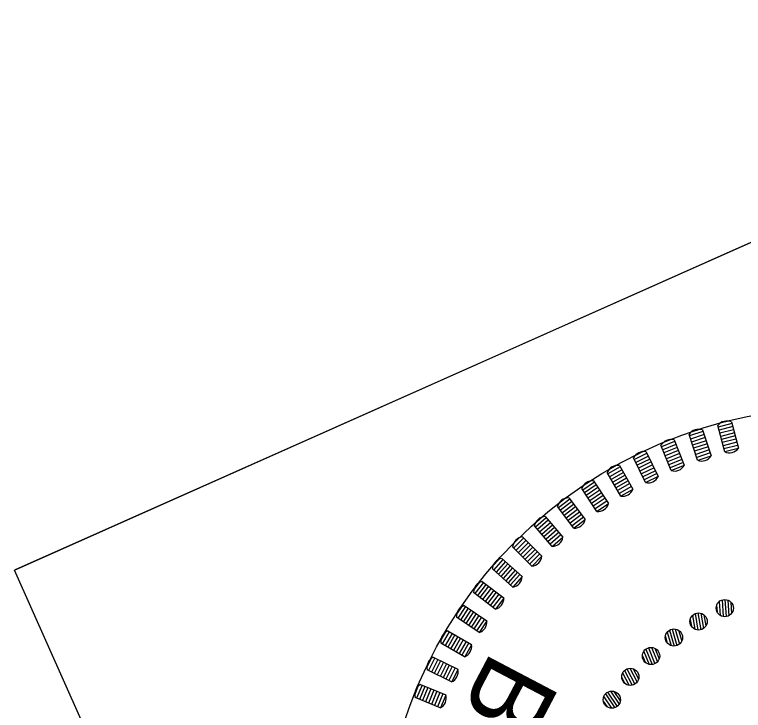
# Model space of a CAD drawing. Extents: x 885268 to 886953, y 552794 to 554777.
# Drawn here: x 886759.5 to 886819.5, y 553269.8 to 553327.1 of the extents above; entities that cross this region are included whole.
import ezdxf

# ---------------------------------------------------------------- set-up
doc = ezdxf.new("R2010")
doc.units = 0
doc.layers.add('Sheet PE Seal Cell', color=7, linetype='Continuous')
doc.layers.add('Sheet Plan CELL', color=7, linetype='Continuous')

msp = doc.modelspace()

# ---------------------------------------------------------------- linework, layer by layer
at = {"layer": 'Sheet PE Seal Cell'}
for p, q in [((886817.956, 553291.104), (886817.391, 553293.28)), ((886818.551, 553293.439), (886817.426, 553293.147)), ((886818.265, 553293.639), (886817.579, 553293.461)), ((886818.517, 553293.572), (886819.082, 553291.396)), ((886816.169, 553292.776), (886815.065, 553292.411)), ((886815.87, 553292.957), (886815.197, 553292.734)), ((886816.126, 553292.906), (886816.833, 553290.772)), ((886818.618, 553293.183), (886817.493, 553292.89)), ((886818.685, 553292.926), (886817.559, 553292.634)), ((886818.751, 553292.669), (886817.626, 553292.377)), ((886813.525, 553292.118), (886812.869, 553291.851)), ((886813.784, 553292.084), (886814.631, 553290.002)), ((886815.729, 553290.407), (886815.022, 553292.541)), ((886816.253, 553292.525), (886815.149, 553292.159)), ((886816.336, 553292.273), (886815.232, 553291.907)), ((886818.818, 553292.412), (886817.692, 553292.12)), ((886818.885, 553292.155), (886817.759, 553291.863)), ((886813.554, 553289.564), (886812.707, 553291.647)), ((886813.836, 553291.958), (886812.758, 553291.52)), ((886813.936, 553291.712), (886812.858, 553291.274)), ((886814.036, 553291.466), (886812.958, 553291.028)), ((886816.419, 553292.021), (886815.316, 553291.655)), ((886816.503, 553291.769), (886815.399, 553291.403)), ((886816.586, 553291.517), (886815.483, 553291.151)), ((886818.951, 553291.898), (886817.826, 553291.606)), ((886819.018, 553291.641), (886817.892, 553291.349)), ((886811.562, 553290.986), (886810.516, 553290.478)), ((886811.241, 553291.126), (886810.604, 553290.816)), ((886811.502, 553291.109), (886812.484, 553289.087)), ((886814.135, 553291.22), (886813.058, 553290.782)), ((886814.235, 553290.974), (886813.158, 553290.536)), ((886816.67, 553291.265), (886815.566, 553290.899)), ((886816.753, 553291.013), (886815.65, 553290.648)), ((886819.071, 553291.381), (886817.973, 553291.096)), ((886811.438, 553288.579), (886810.456, 553290.601)), ((886811.677, 553290.748), (886810.632, 553290.239)), ((886811.793, 553290.509), (886810.748, 553290.001)), ((886811.909, 553290.27), (886810.863, 553289.762)), ((886814.335, 553290.728), (886813.258, 553290.291)), ((886814.435, 553290.483), (886813.358, 553290.045)), ((886814.535, 553290.237), (886813.458, 553289.799)), ((886816.823, 553290.757), (886815.747, 553290.4)), ((886809.357, 553289.867), (886808.346, 553289.291)), ((886809.028, 553289.985), (886808.412, 553289.634)), ((886809.488, 553289.636), (886808.478, 553289.06)), ((886809.289, 553289.986), (886810.403, 553288.033)), ((886812.025, 553290.032), (886810.979, 553289.523)), ((886812.141, 553289.793), (886811.095, 553289.285)), ((886814.622, 553289.986), (886813.571, 553289.559)), ((886809.393, 553287.457), (886808.279, 553289.41)), ((886809.619, 553289.406), (886808.609, 553288.83)), ((886809.751, 553289.175), (886808.741, 553288.599)), ((886812.257, 553289.554), (886811.211, 553289.046)), ((886812.373, 553289.316), (886811.327, 553288.807)), ((886812.476, 553289.071), (886811.456, 553288.575)), ((886807.23, 553288.604), (886806.261, 553287.962)), ((886806.894, 553288.7), (886806.304, 553288.309)), ((886807.155, 553288.718), (886808.395, 553286.843)), ((886809.882, 553288.945), (886808.872, 553288.369)), ((886810.014, 553288.714), (886809.004, 553288.138)), ((886810.145, 553288.484), (886809.135, 553287.908)), ((886807.426, 553286.202), (886806.185, 553288.076)), ((886807.377, 553288.383), (886806.407, 553287.741)), ((886807.523, 553288.161), (886806.553, 553287.52)), ((886807.67, 553287.94), (886806.7, 553287.298)), ((886810.277, 553288.253), (886809.267, 553287.677)), ((886810.396, 553288.016), (886809.411, 553287.454)), ((886804.851, 553287.277), (886804.287, 553286.848)), ((886805.109, 553287.312), (886806.471, 553285.524)), ((886807.816, 553287.719), (886806.846, 553287.077)), ((886807.962, 553287.497), (886806.993, 553286.856)), ((886808.109, 553287.276), (886807.139, 553286.634)), ((886805.192, 553287.203), (886804.267, 553286.499)), ((886805.353, 553286.992), (886804.428, 553286.288)), ((886805.514, 553286.781), (886804.588, 553286.077)), ((886808.255, 553287.055), (886807.286, 553286.413)), ((886808.39, 553286.826), (886807.444, 553286.2)), ((886805.546, 553284.819), (886804.184, 553286.608)), ((886805.674, 553286.57), (886804.749, 553285.866)), ((886805.835, 553286.359), (886804.91, 553285.654)), ((886805.996, 553286.148), (886805.071, 553285.443)), ((886802.906, 553285.722), (886802.372, 553285.257)), ((886803.251, 553285.671), (886802.375, 553284.907)), ((886803.426, 553285.471), (886802.549, 553284.707)), ((886803.161, 553285.774), (886804.638, 553284.08)), ((886806.157, 553285.937), (886805.231, 553285.232)), ((886806.317, 553285.725), (886805.392, 553285.021)), ((886806.467, 553285.506), (886805.564, 553284.819)), ((886803.762, 553283.316), (886802.285, 553285.01)), ((886803.6, 553285.271), (886802.723, 553284.507)), ((886803.774, 553285.071), (886802.898, 553284.307)), ((886803.949, 553284.871), (886803.072, 553284.107)), ((886804.123, 553284.671), (886803.246, 553283.907)), ((886804.297, 553284.471), (886803.421, 553283.707)), ((886804.472, 553284.271), (886803.595, 553283.507)), ((886801.067, 553284.042), (886800.565, 553283.542)), ((886801.416, 553284.014), (886800.591, 553283.194)), ((886801.603, 553283.826), (886800.779, 553283.006)), ((886801.79, 553283.638), (886800.966, 553282.818)), ((886801.319, 553284.111), (886802.905, 553282.518)), ((886804.635, 553284.061), (886803.78, 553283.316)), ((886802.081, 553281.697), (886800.495, 553283.291)), ((886801.977, 553283.45), (886801.153, 553282.63)), ((886802.164, 553283.262), (886801.34, 553282.441)), ((886802.352, 553283.074), (886801.527, 553282.253)), ((886802.539, 553282.886), (886801.714, 553282.065)), ((886802.726, 553282.697), (886801.902, 553281.877)), ((886802.903, 553282.499), (886802.099, 553281.699)), ((886799.344, 553282.244), (886798.876, 553281.712)), ((886799.694, 553282.239), (886798.925, 553281.366)), ((886799.893, 553282.064), (886799.125, 553281.191)), ((886800.092, 553281.889), (886799.324, 553281.016)), ((886799.591, 553282.33), (886801.278, 553280.845)), ((886800.51, 553279.972), (886798.823, 553281.457)), ((886800.291, 553281.713), (886799.523, 553280.84)), ((886800.49, 553281.538), (886799.722, 553280.665)), ((886800.69, 553281.363), (886799.921, 553280.49)), ((886800.889, 553281.187), (886800.121, 553280.315)), ((886801.088, 553281.012), (886800.32, 553280.139)), ((886801.278, 553280.826), (886800.528, 553279.975)), ((886797.744, 553280.336), (886797.312, 553279.775)), ((886798.093, 553280.355), (886797.384, 553279.433)), ((886798.303, 553280.193), (886797.594, 553279.271)), ((886798.513, 553280.031), (886797.805, 553279.109)), ((886797.984, 553280.438), (886799.766, 553279.068)), ((886799.057, 553278.146), (886797.275, 553279.516)), ((886798.724, 553279.869), (886798.015, 553278.947)), ((886798.934, 553279.708), (886798.225, 553278.786)), ((886799.144, 553279.546), (886798.436, 553278.624)), ((886799.355, 553279.384), (886798.646, 553278.462)), ((886799.565, 553279.222), (886798.856, 553278.3)), ((886799.767, 553279.049), (886799.075, 553278.15)), ((886817.739, 553278.904), (886817.835, 553277.534)), ((886817.973, 553278.941), (886818.072, 553277.531)), ((886818.213, 553278.895), (886818.304, 553277.61)), ((886796.273, 553278.327), (886795.879, 553277.738)), ((886796.62, 553278.368), (886795.973, 553277.401)), ((886796.84, 553278.221), (886796.194, 553277.254)), ((886796.506, 553278.444), (886798.375, 553277.195)), ((886817.295, 553278.472), (886817.336, 553277.901)), ((886817.511, 553278.778), (886817.592, 553277.627)), ((886818.461, 553278.735), (886818.527, 553277.803)), ((886797.061, 553278.073), (886796.415, 553277.106)), ((886797.282, 553277.926), (886796.635, 553276.959)), ((886797.502, 553277.778), (886796.856, 553276.811)), ((886797.723, 553277.631), (886797.076, 553276.664)), ((886815.299, 553277.628), (886815.5, 553276.492)), ((886815.512, 553277.777), (886815.751, 553276.425)), ((886815.742, 553277.838), (886815.988, 553276.446)), ((886815.985, 553277.817), (886816.209, 553276.549)), ((886816.249, 553277.685), (886816.411, 553276.764)), ((886797.728, 553276.228), (886795.86, 553277.478)), ((886797.943, 553277.483), (886797.297, 553276.516)), ((886798.164, 553277.336), (886797.517, 553276.369)), ((886798.376, 553277.176), (886797.746, 553276.233)), ((886815.117, 553277.3), (886815.216, 553276.737)), ((886813.416, 553276.424), (886813.795, 553275.103)), ((886813.638, 553276.508), (886814.028, 553275.15)), ((886813.882, 553276.513), (886814.238, 553275.275)), ((886794.938, 553276.224), (886794.584, 553275.611)), ((886795.281, 553276.289), (886794.7, 553275.281)), ((886795.511, 553276.156), (886794.93, 553275.149)), ((886795.741, 553276.024), (886795.16, 553275.016)), ((886795.163, 553276.357), (886797.11, 553275.234)), ((886795.971, 553275.891), (886795.39, 553274.884)), ((886813.072, 553275.908), (886813.23, 553275.358)), ((886813.219, 553276.253), (886813.538, 553275.144)), ((886814.158, 553276.408), (886814.416, 553275.51)), ((886796.529, 553274.226), (886794.582, 553275.35)), ((886796.201, 553275.758), (886795.62, 553274.751)), ((886796.431, 553275.626), (886795.85, 553274.618)), ((886796.66, 553275.493), (886796.079, 553274.486)), ((886796.89, 553275.361), (886796.309, 553274.353)), ((886797.113, 553275.215), (886796.546, 553274.233)), ((886811.295, 553274.667), (886811.727, 553273.598)), ((886811.473, 553274.858), (886811.988, 553273.585)), ((886811.684, 553274.965), (886812.214, 553273.655)), ((886811.927, 553274.996), (886812.41, 553273.802)), ((886812.212, 553274.921), (886812.563, 553274.054)), ((886793.745, 553274.039), (886793.432, 553273.403)), ((886794.083, 553274.125), (886793.57, 553273.082)), ((886793.96, 553274.186), (886795.978, 553273.194)), ((886811.185, 553274.309), (886811.399, 553273.779)), ((886794.321, 553274.008), (886793.808, 553272.965)), ((886794.56, 553273.891), (886794.046, 553272.848)), ((886794.798, 553273.774), (886794.284, 553272.731)), ((886795.036, 553273.657), (886794.523, 553272.613)), ((886795.274, 553273.54), (886794.761, 553272.496)), ((886795.512, 553273.423), (886794.999, 553272.379)), ((886795.465, 553272.15), (886793.447, 553273.142)), ((886795.75, 553273.306), (886795.237, 553272.262)), ((886795.982, 553273.175), (886795.481, 553272.158)), ((886809.547, 553272.89), (886810.088, 553271.872)), ((886809.704, 553273.098), (886810.349, 553271.886)), ((886809.903, 553273.226), (886810.567, 553271.979)), ((886810.141, 553273.282), (886810.746, 553272.145)), ((886810.432, 553273.238), (886810.872, 553272.412)), ((886809.474, 553272.522), (886809.743, 553272.017)), ((886792.699, 553271.779), (886792.429, 553271.124)), ((886793.031, 553271.888), (886792.588, 553270.812)), ((886793.276, 553271.786), (886792.833, 553270.711)), ((886792.904, 553271.94), (886794.983, 553271.083)), ((886793.522, 553271.685), (886793.078, 553270.61)), ((886793.767, 553271.584), (886793.324, 553270.509)), ((886794.012, 553271.483), (886793.569, 553270.408)), ((886794.258, 553271.382), (886793.814, 553270.307)), ((886794.503, 553271.281), (886794.06, 553270.206)), ((886794.748, 553271.18), (886794.305, 553270.105)), ((886794.988, 553271.065), (886794.556, 553270.017)), ((886808.128, 553271.163), (886808.897, 553270.024)), ((886808.313, 553271.311), (886809.103, 553270.14)), ((886808.544, 553271.392), (886809.264, 553270.324)), ((886808.838, 553271.378), (886809.362, 553270.603)), ((886794.54, 553270.008), (886792.461, 553270.865)), ((886807.96, 553270.566), (886808.281, 553270.092)), ((886807.994, 553270.939), (886808.639, 553269.983))]:
    msp.add_line(p, q, dxfattribs=at)
for centre, radius in [((886827.4, 553257.054), 37.726), ((886817.963, 553278.232), 0.709), ((886815.805, 553277.132), 0.709), ((886813.775, 553275.812), 0.709), ((886811.893, 553274.287), 0.709), ((886810.182, 553272.575), 0.709), ((886808.658, 553270.692), 0.709)]:
    msp.add_circle(centre, radius, dxfattribs=at)
for centre, radius, start, end in [((886818.146, 553292.686), 0.96, 67.27471, 141.81568), ((886815.814, 553291.998), 0.96, 71.06419, 145.60515), ((886813.533, 553291.158), 0.96, 74.85366, 149.39463), ((886811.313, 553290.168), 0.96, 78.64313, 153.1841), ((886818.342, 553291.933), 0.914, 245.04845, 324.04194), ((886816.059, 553291.259), 0.914, 248.83792, 327.83142), ((886809.162, 553289.034), 0.96, 82.43261, 156.97358), ((886813.826, 553290.436), 0.914, 252.6274, 331.62089), ((886811.653, 553289.468), 0.914, 256.41687, 335.41036), ((886807.091, 553287.76), 0.96, 86.22208, 160.76305), ((886809.548, 553288.358), 0.914, 260.20635, 339.19984), ((886805.109, 553286.352), 0.96, 90.01155, 164.55252), ((886807.521, 553287.111), 0.914, 263.99582, 342.98931), ((886803.225, 553284.816), 0.96, 93.80103, 168.342), ((886805.581, 553285.733), 0.914, 267.78529, 346.77878), ((886801.446, 553283.159), 0.96, 97.5905, 172.13147), ((886803.736, 553284.229), 0.914, 271.57477, 350.56826), ((886801.995, 553282.608), 0.914, 275.36424, 354.35773), ((886799.78, 553281.389), 0.96, 101.37998, 175.92094), ((886800.365, 553280.874), 0.914, 279.15371, 358.14721), ((886798.235, 553279.511), 0.96, 105.16945, 179.71042), ((886798.853, 553279.037), 0.914, 282.94319, 1.93668), ((886796.818, 553277.536), 0.96, 108.95892, 183.49989), ((886797.465, 553277.103), 0.914, 286.73266, 5.72615), ((886795.534, 553275.472), 0.96, 112.7484, 187.28936), ((886796.208, 553275.083), 0.914, 290.52213, 9.51563), ((886794.389, 553273.327), 0.96, 116.53787, 191.07884), ((886795.088, 553272.983), 0.914, 294.31161, 13.3051), ((886793.389, 553271.111), 0.96, 120.32734, 194.86831), ((886794.109, 553270.814), 0.914, 298.10108, 17.09457)]:
    msp.add_arc(centre, radius, start, end, dxfattribs=at)
at = {"layer": 'Sheet Plan CELL'}
msp.add_line((886862.251, 553327.122), (886759.527, 553281.377), dxfattribs=at)
msp.add_lwpolyline([(886862.251, 553327.122), (886902.932, 553235.771), (886800.162, 553190.005), (886759.481, 553281.356)], close=True, dxfattribs=at)

# ---------------------------------------------------------------- texts
at = {"layer": 'Sheet PE Seal Cell'}
msp.add_text('B', height=6.368, rotation=242.25562, dxfattribs=at).set_placement((886798.815, 553274.866))

doc.saveas('drawing.dxf')
